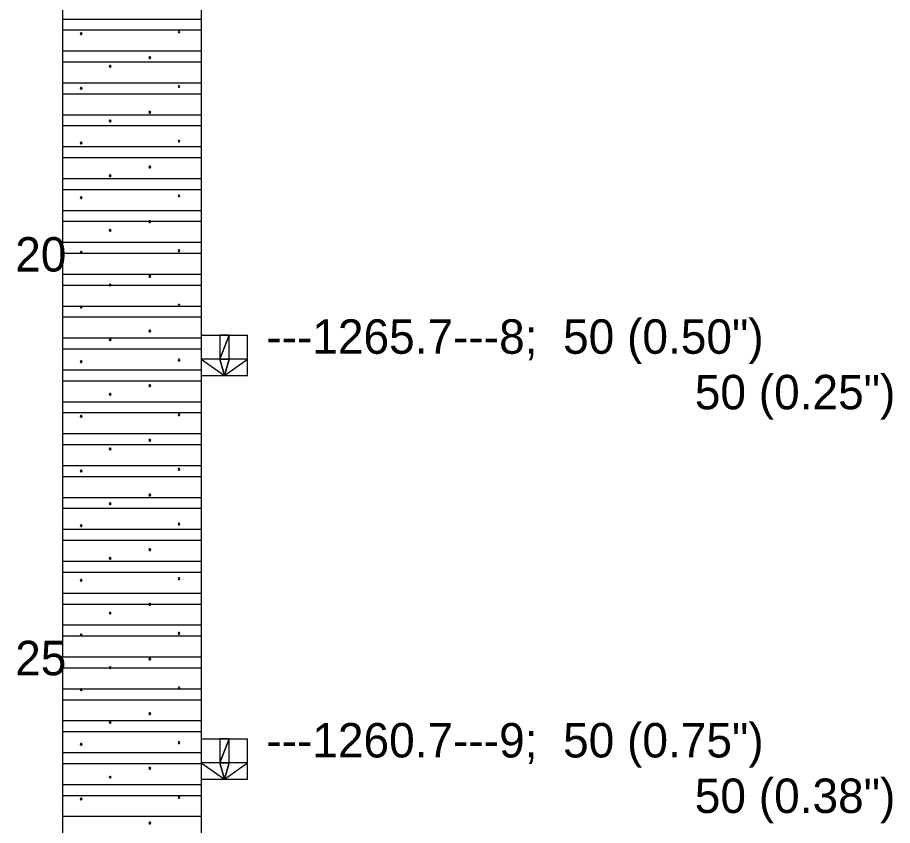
# Model space of a CAD drawing. Extents: x -6 to 173, y 24 to 64.
# Drawn here: x 101.536 to 104.687, y 41.654 to 44.563 of the extents above; entities that cross this region are included whole.
import ezdxf

# ---------------------------------------------------------------- set-up
doc = ezdxf.new("R2010")
doc.units = 0

msp = doc.modelspace()

# ---------------------------------------------------------------- linework, layer by layer
for points in [[(101.6976, 49.5245), (101.6976, 39.0593)], [(102.1976, 49.5245), (102.1976, 39.0593)], [(101.6976, 44.5578), (102.1976, 44.5578)], [(101.6976, 44.5184), (102.1976, 44.5184)], [(101.768, 44.5051), (101.7664, 44.5079), (101.7631, 44.5079), (101.7614, 44.5051), (101.7631, 44.5022), (101.7664, 44.5022), (101.768, 44.5051)], [(102.1208, 44.5115), (102.1191, 44.5144), (102.1158, 44.5144), (102.1142, 44.5115), (102.1158, 44.5087), (102.1191, 44.5087), (102.1208, 44.5115)], [(101.6976, 44.443), (102.1976, 44.443)], [(102.0152, 44.419), (102.0136, 44.4218), (102.0103, 44.4218), (102.0087, 44.419), (102.0103, 44.4162), (102.0136, 44.4162), (102.0152, 44.419)], [(101.6976, 44.4036), (102.1976, 44.4036)], [(101.8727, 44.3871), (101.871, 44.39), (101.8677, 44.39), (101.8661, 44.3872), (101.8677, 44.3843), (101.871, 44.3843), (101.8727, 44.3871)], [(101.6976, 44.3281), (102.1976, 44.3281)], [(102.1208, 44.3147), (102.1191, 44.3176), (102.1158, 44.3176), (102.1142, 44.3147), (102.1158, 44.3119), (102.1191, 44.3119), (102.1208, 44.3147)], [(101.6976, 44.2888), (102.1976, 44.2888)], [(101.768, 44.3082), (101.7664, 44.311), (101.7631, 44.311), (101.7614, 44.3082), (101.7631, 44.3053), (101.7664, 44.3053), (101.768, 44.3082)], [(102.0152, 44.2222), (102.0136, 44.225), (102.0103, 44.225), (102.0087, 44.2222), (102.0103, 44.2194), (102.0136, 44.2194), (102.0152, 44.2222)], [(101.6976, 44.2133), (102.1976, 44.2133)], [(101.8727, 44.1903), (101.871, 44.1932), (101.8677, 44.1932), (101.8661, 44.1904), (101.8677, 44.1875), (101.871, 44.1875), (101.8727, 44.1903)], [(101.6976, 44.1739), (102.1976, 44.1739)], [(101.6976, 44.0985), (102.1976, 44.0985)], [(101.768, 44.1114), (101.7664, 44.1142), (101.7631, 44.1142), (101.7614, 44.1114), (101.7631, 44.1085), (101.7664, 44.1085), (101.768, 44.1114)], [(102.1208, 44.1178), (102.1191, 44.1207), (102.1158, 44.1207), (102.1142, 44.1178), (102.1158, 44.115), (102.1191, 44.115), (102.1208, 44.1178)], [(101.6976, 44.0591), (102.1976, 44.0591)], [(102.0152, 44.0253), (102.0136, 44.0281), (102.0103, 44.0281), (102.0087, 44.0253), (102.0103, 44.0225), (102.0136, 44.0225), (102.0152, 44.0253)], [(101.6976, 43.9837), (102.1976, 43.9837)], [(101.8727, 43.9934), (101.871, 43.9963), (101.8677, 43.9963), (101.8661, 43.9935), (101.8677, 43.9906), (101.871, 43.9906), (101.8727, 43.9934)], [(101.6976, 43.9443), (102.1976, 43.9443)], [(101.768, 43.9145), (101.7664, 43.9173), (101.7631, 43.9173), (101.7614, 43.9145), (101.7631, 43.9116), (101.7664, 43.9116), (101.768, 43.9145)], [(102.1208, 43.921), (102.1191, 43.9239), (102.1158, 43.9239), (102.1142, 43.921), (102.1158, 43.9182), (102.1191, 43.9182), (102.1208, 43.921)], [(101.6976, 43.8688), (102.1976, 43.8688)], [(101.6976, 43.8295), (102.1976, 43.8295)], [(102.0152, 43.8285), (102.0136, 43.8313), (102.0103, 43.8313), (102.0087, 43.8285), (102.0103, 43.8257), (102.0136, 43.8257), (102.0152, 43.8285)], [(101.8727, 43.7966), (101.871, 43.7995), (101.8677, 43.7995), (101.8661, 43.7967), (101.8677, 43.7938), (101.871, 43.7938), (101.8727, 43.7966)], [(101.6976, 43.754), (102.1976, 43.754)], [(101.6976, 43.7146), (102.1976, 43.7146)], [(101.768, 43.7177), (101.7664, 43.7205), (101.7631, 43.7205), (101.7614, 43.7177), (101.7631, 43.7148), (101.7664, 43.7148), (101.768, 43.7177)], [(102.1208, 43.7241), (102.1191, 43.727), (102.1158, 43.727), (102.1142, 43.7241), (102.1158, 43.7213), (102.1191, 43.7213), (102.1208, 43.7241)], [(101.6976, 43.6392), (102.1976, 43.6392)], [(102.0152, 43.6316), (102.0136, 43.6344), (102.0103, 43.6344), (102.0087, 43.6316), (102.0103, 43.6288), (102.0136, 43.6288), (102.0152, 43.6316)], [(101.6976, 43.5998), (102.1976, 43.5998)], [(101.8727, 43.5997), (101.871, 43.6026), (101.8677, 43.6026), (101.8661, 43.5998), (101.8677, 43.5969), (101.871, 43.5969), (101.8727, 43.5997)], [(102.1208, 43.5273), (102.1191, 43.5302), (102.1158, 43.5302), (102.1142, 43.5273), (102.1158, 43.5245), (102.1191, 43.5245), (102.1208, 43.5273)], [(101.6976, 43.5243), (102.1976, 43.5243)], [(101.768, 43.5208), (101.7664, 43.5236), (101.7631, 43.5236), (101.7614, 43.5208), (101.7631, 43.5179), (101.7664, 43.5179), (101.768, 43.5208)], [(101.6976, 43.485), (102.1976, 43.485)], [(102.0152, 43.4348), (102.0136, 43.4376), (102.0103, 43.4376), (102.0087, 43.4348), (102.0103, 43.432), (102.0136, 43.432), (102.0152, 43.4348)], [(101.6976, 43.4095), (102.1976, 43.4095)], [(101.8727, 43.4029), (101.871, 43.4058), (101.8677, 43.4058), (101.8661, 43.403), (101.8677, 43.4001), (101.871, 43.4001), (101.8727, 43.4029)], [(102.1976, 43.4198), (102.3643, 43.4198)], [(102.3643, 43.2745), (102.3643, 43.4198)], [(101.6976, 43.3701), (102.1976, 43.3701)], [(101.768, 43.3239), (101.7664, 43.3268), (101.7631, 43.3268), (101.7614, 43.3239), (101.7631, 43.3211), (101.7664, 43.3211), (101.768, 43.3239)], [(102.1208, 43.3304), (102.1191, 43.3333), (102.1158, 43.3333), (102.1142, 43.3304), (102.1158, 43.3276), (102.1191, 43.3276), (102.1208, 43.3304)], [(101.6976, 43.2947), (102.1976, 43.2947)], [(102.1976, 43.2745), (102.3643, 43.2745)], [(101.6976, 43.2553), (102.1976, 43.2553)], [(102.0152, 43.2379), (102.0136, 43.2407), (102.0103, 43.2407), (102.0087, 43.2379), (102.0103, 43.2351), (102.0136, 43.2351), (102.0152, 43.2379)], [(101.6976, 43.1799), (102.1976, 43.1799)], [(101.8727, 43.206), (101.871, 43.2089), (101.8677, 43.2089), (101.8661, 43.2061), (101.8677, 43.2032), (101.871, 43.2032), (101.8727, 43.206)], [(101.6976, 43.1405), (102.1976, 43.1405)], [(101.768, 43.1271), (101.7664, 43.1299), (101.7631, 43.1299), (101.7614, 43.1271), (101.7631, 43.1242), (101.7664, 43.1242), (101.768, 43.1271)], [(102.1208, 43.1336), (102.1191, 43.1365), (102.1158, 43.1365), (102.1142, 43.1336), (102.1158, 43.1308), (102.1191, 43.1308), (102.1208, 43.1336)], [(101.6976, 43.065), (102.1976, 43.065)], [(101.6976, 43.0257), (102.1976, 43.0257)], [(102.0152, 43.0411), (102.0136, 43.0439), (102.0103, 43.0439), (102.0087, 43.0411), (102.0103, 43.0383), (102.0136, 43.0383), (102.0152, 43.0411)], [(101.8727, 43.0092), (101.871, 43.0121), (101.8677, 43.0121), (101.8661, 43.0093), (101.8677, 43.0064), (101.871, 43.0064), (101.8727, 43.0092)], [(101.6976, 42.9502), (102.1976, 42.9502)], [(101.768, 42.9302), (101.7664, 42.9331), (101.7631, 42.9331), (101.7614, 42.9302), (101.7631, 42.9274), (101.7664, 42.9274), (101.768, 42.9302)], [(102.1208, 42.9367), (102.1191, 42.9396), (102.1158, 42.9396), (102.1142, 42.9367), (102.1158, 42.9339), (102.1191, 42.9339), (102.1208, 42.9367)], [(101.6976, 42.9108), (102.1976, 42.9108)], [(101.6976, 42.8354), (102.1976, 42.8354)], [(102.0152, 42.8442), (102.0136, 42.847), (102.0103, 42.847), (102.0087, 42.8442), (102.0103, 42.8414), (102.0136, 42.8414), (102.0152, 42.8442)], [(101.8727, 42.8123), (101.871, 42.8152), (101.8677, 42.8152), (101.8661, 42.8124), (101.8677, 42.8095), (101.871, 42.8095), (101.8727, 42.8123)], [(101.6976, 42.796), (102.1976, 42.796)], [(102.1208, 42.7399), (102.1191, 42.7428), (102.1158, 42.7428), (102.1142, 42.7399), (102.1158, 42.7371), (102.1191, 42.7371), (102.1208, 42.7399)], [(101.6976, 42.7205), (102.1976, 42.7205)], [(101.768, 42.7334), (101.7664, 42.7362), (101.7631, 42.7362), (101.7614, 42.7334), (101.7631, 42.7305), (101.7664, 42.7305), (101.768, 42.7334)], [(101.6976, 42.6812), (102.1976, 42.6812)], [(102.0152, 42.6474), (102.0136, 42.6502), (102.0103, 42.6502), (102.0087, 42.6474), (102.0103, 42.6446), (102.0136, 42.6446), (102.0152, 42.6474)], [(101.8727, 42.6155), (101.871, 42.6184), (101.8677, 42.6184), (101.8661, 42.6156), (101.8677, 42.6127), (101.871, 42.6127), (101.8727, 42.6155)], [(101.6976, 42.6057), (102.1976, 42.6057)], [(101.6976, 42.5663), (102.1976, 42.5663)], [(101.768, 42.5365), (101.7664, 42.5394), (101.7631, 42.5394), (101.7614, 42.5365), (101.7631, 42.5337), (101.7664, 42.5337), (101.768, 42.5365)], [(102.1208, 42.543), (102.1191, 42.5459), (102.1158, 42.5459), (102.1142, 42.543), (102.1158, 42.5402), (102.1191, 42.5402), (102.1208, 42.543)], [(101.6976, 42.4909), (102.1976, 42.4909)], [(102.0152, 42.4505), (102.0136, 42.4533), (102.0103, 42.4533), (102.0087, 42.4505), (102.0103, 42.4477), (102.0136, 42.4477), (102.0152, 42.4505)], [(101.6976, 42.4515), (102.1976, 42.4515)], [(101.8727, 42.4186), (101.871, 42.4215), (101.8677, 42.4215), (101.8661, 42.4187), (101.8677, 42.4158), (101.871, 42.4158), (101.8727, 42.4186)], [(101.6976, 42.376), (102.1976, 42.376)], [(101.6976, 42.3367), (102.1976, 42.3367)], [(101.768, 42.3397), (101.7664, 42.3425), (101.7631, 42.3425), (101.7614, 42.3397), (101.7631, 42.3368), (101.7664, 42.3368), (101.768, 42.3397)], [(102.1208, 42.3462), (102.1191, 42.3491), (102.1158, 42.3491), (102.1142, 42.3462), (102.1158, 42.3434), (102.1191, 42.3434), (102.1208, 42.3462)], [(101.6976, 42.2612), (102.1976, 42.2612)], [(102.0152, 42.2537), (102.0136, 42.2565), (102.0103, 42.2565), (102.0087, 42.2537), (102.0103, 42.2509), (102.0136, 42.2509), (102.0152, 42.2537)], [(101.6976, 42.2218), (102.1976, 42.2218)], [(101.8727, 42.2218), (101.871, 42.2247), (101.8677, 42.2247), (101.8661, 42.2218), (101.8677, 42.219), (101.871, 42.219), (101.8727, 42.2218)], [(101.6976, 42.1464), (102.1976, 42.1464)], [(101.768, 42.1428), (101.7664, 42.1457), (101.7631, 42.1457), (101.7614, 42.1428), (101.7631, 42.14), (101.7664, 42.14), (101.768, 42.1428)], [(102.1208, 42.1493), (102.1191, 42.1522), (102.1158, 42.1522), (102.1142, 42.1493), (102.1158, 42.1465), (102.1191, 42.1465), (102.1208, 42.1493)], [(101.6976, 42.107), (102.1976, 42.107)], [(102.0152, 42.0568), (102.0136, 42.0596), (102.0103, 42.0596), (102.0087, 42.0568), (102.0103, 42.054), (102.0136, 42.054), (102.0152, 42.0568)], [(101.6976, 42.0316), (102.1976, 42.0316)], [(101.8727, 42.0249), (101.871, 42.0278), (101.8677, 42.0278), (101.8661, 42.025), (101.8677, 42.0221), (101.871, 42.0221), (101.8727, 42.0249)], [(101.6976, 41.9922), (102.1976, 41.9922)], [(102.1208, 41.9525), (102.1191, 41.9554), (102.1158, 41.9554), (102.1142, 41.9525), (102.1158, 41.9497), (102.1191, 41.9497), (102.1208, 41.9525)], [(102.1976, 41.9663), (102.3643, 41.9663)], [(102.3643, 41.821), (102.3643, 41.9663)], [(101.768, 41.946), (101.7664, 41.9488), (101.7631, 41.9488), (101.7614, 41.946), (101.7631, 41.9431), (101.7664, 41.9431), (101.768, 41.946)], [(101.6976, 41.9167), (102.1976, 41.9167)], [(101.6976, 41.8774), (102.1976, 41.8774)], [(102.0152, 41.86), (102.0136, 41.8628), (102.0103, 41.8628), (102.0087, 41.86), (102.0103, 41.8572), (102.0136, 41.8572), (102.0152, 41.86)], [(101.8727, 41.8281), (101.871, 41.831), (101.8677, 41.831), (101.8661, 41.8281), (101.8677, 41.8253), (101.871, 41.8253), (101.8727, 41.8281)], [(101.6976, 41.8019), (102.1976, 41.8019)], [(102.1976, 41.821), (102.3643, 41.821)], [(101.6976, 41.7625), (102.1976, 41.7625)], [(101.768, 41.7491), (101.7664, 41.752), (101.7631, 41.752), (101.7614, 41.7491), (101.7631, 41.7463), (101.7664, 41.7463), (101.768, 41.7491)], [(102.1208, 41.7556), (102.1191, 41.7585), (102.1158, 41.7585), (102.1142, 41.7556), (102.1158, 41.7528), (102.1191, 41.7528), (102.1208, 41.7556)], [(101.6976, 41.6871), (102.1976, 41.6871)], [(102.0152, 41.6631), (102.0136, 41.6659), (102.0103, 41.6659), (102.0087, 41.6631), (102.0103, 41.6603), (102.0136, 41.6603), (102.0152, 41.6631)]]:
    msp.add_lwpolyline(points)
for points in [[(102.2643, 43.3326), (102.2976, 43.3326), (102.2976, 43.4198), (102.2643, 43.3326)], [(102.2643, 43.3326), (102.2976, 43.4198), (102.2643, 43.4198), (102.2643, 43.3326)], [(102.2643, 43.3326), (102.1976, 43.3326), (102.2809, 43.2745), (102.2643, 43.3326)], [(102.2643, 43.3326), (102.2809, 43.2745), (102.2976, 43.3326), (102.2643, 43.3326)], [(102.2809, 43.2745), (102.3643, 43.3326), (102.2976, 43.3326), (102.2809, 43.2745)], [(102.2643, 41.8791), (102.2976, 41.8791), (102.2976, 41.9663), (102.2643, 41.8791)], [(102.2643, 41.8791), (102.2976, 41.9663), (102.2643, 41.9663), (102.2643, 41.8791)], [(102.2643, 41.8791), (102.1976, 41.8791), (102.2809, 41.821), (102.2643, 41.8791)], [(102.2643, 41.8791), (102.2809, 41.821), (102.2976, 41.8791), (102.2643, 41.8791)], [(102.2809, 41.821), (102.3643, 41.8791), (102.2976, 41.8791), (102.2809, 41.821)]]:
    msp.add_lwpolyline(points, close=True)

# ---------------------------------------------------------------- texts
for s, p in [('20', (101.5272, 43.6485)), ('---1265.7---8;  50 (0.50")', (102.4317, 43.3525)), ('50 (0.25")', (103.975, 43.1525)), ('25', (101.5272, 42.195)), ('---1260.7---9;  50 (0.75")', (102.4317, 41.899)), ('50 (0.38")', (103.975, 41.699))]:
    msp.add_text(s, height=0.124).set_placement(p)

doc.saveas('drawing.dxf')
